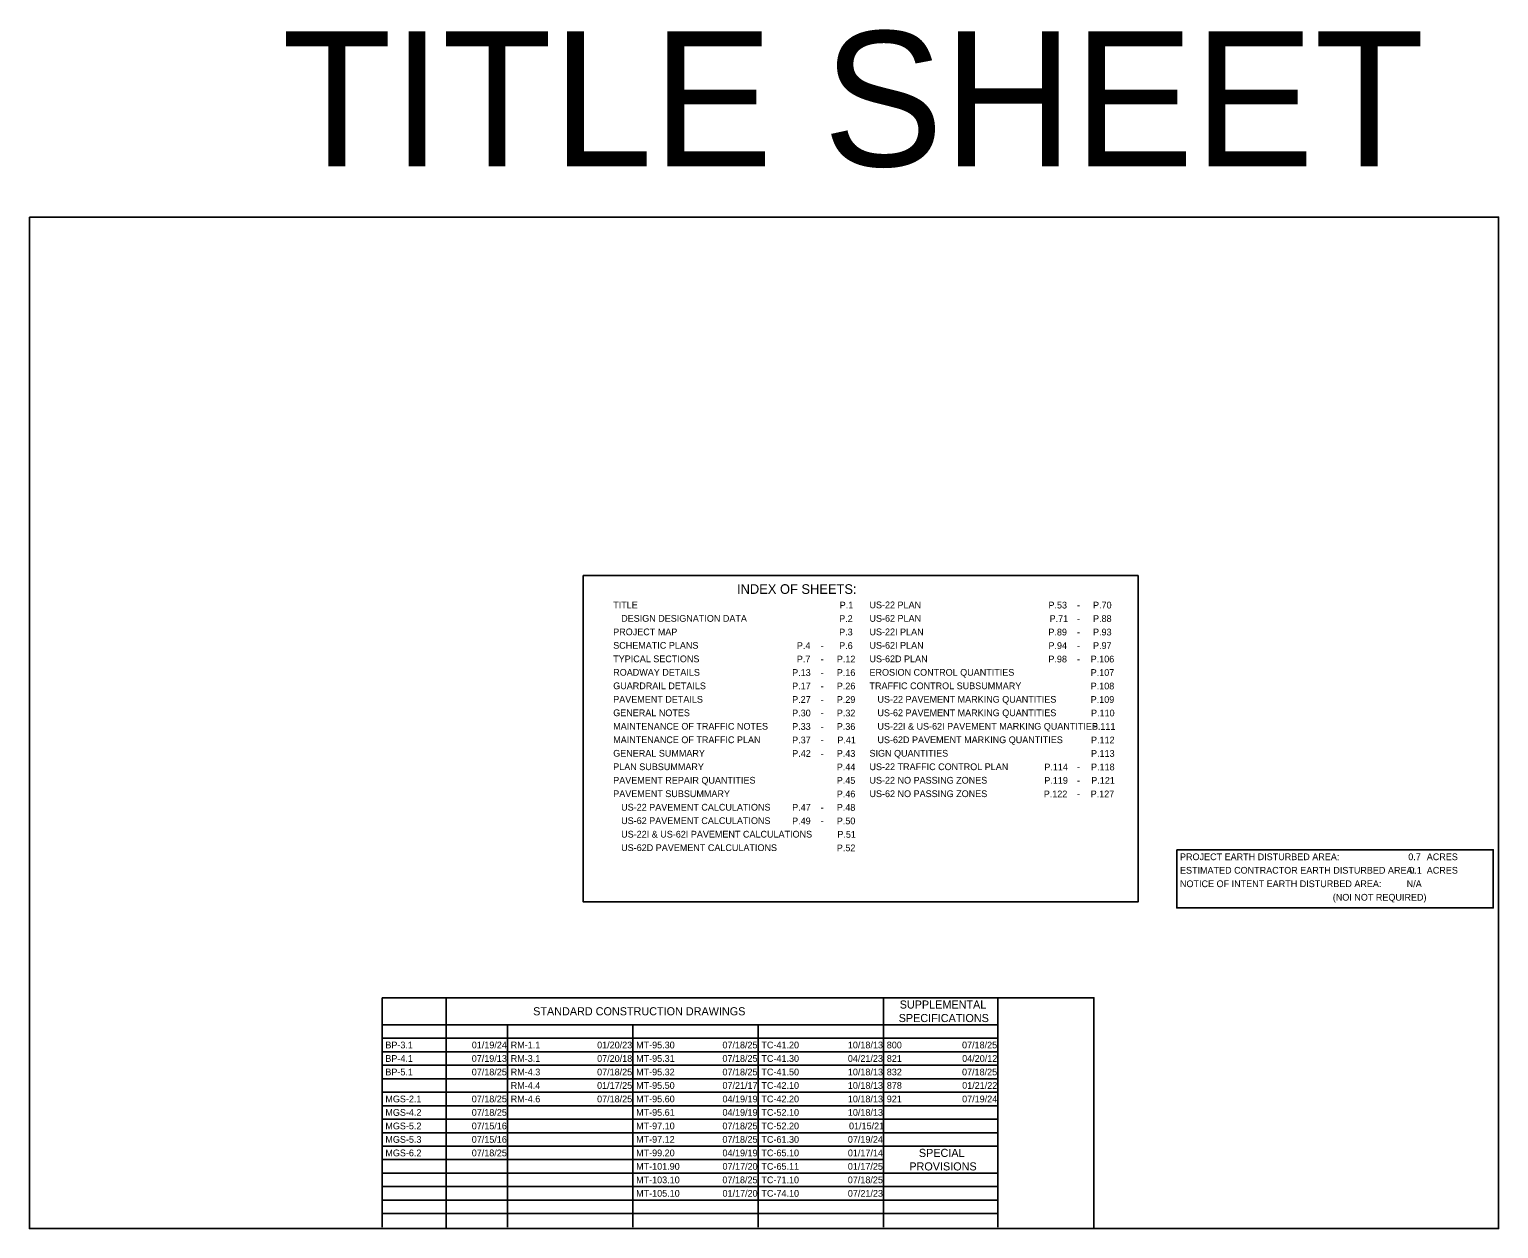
# Model space of a CAD drawing. Extents: x 12522 to 13018, y 1124 to 1902.
# Drawn here: x 12607.42 to 12637.92, y 1828.79 to 1853.69 of the extents above; entities that cross this region are included whole.
import ezdxf

# ---------------------------------------------------------------- set-up
doc = ezdxf.new("R2010")
doc.units = 0
for name, color, linetype in [('SC_Scratch1', 7, 'Continuous'), ('SH_Data', 7, 'Continuous'), ('SH_Text', 7, 'Continuous')]:
    doc.layers.add(name, color=color, linetype=linetype)

msp = doc.modelspace()

# ---------------------------------------------------------------- linework, layer by layer
at = {"layer": 'SC_Scratch1'}
for points in [[(12607.415, 1849.791), (12637.915, 1849.791), (12637.915, 1828.791), (12607.415, 1828.791)], [(12618.914, 1842.346), (12630.432, 1842.346), (12630.432, 1835.575), (12618.914, 1835.575)], [(12631.235, 1836.655), (12637.805, 1836.655), (12637.805, 1835.448), (12631.235, 1835.448)], [(12616.065, 1828.791), (12629.515, 1828.791), (12629.515, 1833.583), (12616.065, 1833.583)]]:
    msp.add_lwpolyline(points, close=True, dxfattribs=at)
at = {"layer": 'SH_Data'}
for p, q in [((12614.739, 1833.583), (12627.52, 1833.583)), ((12614.739, 1833.583), (12614.739, 1828.823)), ((12625.148, 1833.583), (12625.148, 1828.823)), ((12627.52, 1833.583), (12627.52, 1828.823)), ((12614.739, 1833.023), (12627.52, 1833.023)), ((12617.341, 1833.023), (12617.341, 1828.823)), ((12619.944, 1833.023), (12619.944, 1828.823)), ((12622.546, 1833.023), (12622.546, 1828.823)), ((12614.739, 1832.743), (12627.52, 1832.743)), ((12614.739, 1832.463), (12627.52, 1832.463)), ((12614.739, 1832.183), (12627.52, 1832.183)), ((12614.739, 1831.903), (12627.52, 1831.903)), ((12614.739, 1831.623), (12627.52, 1831.623)), ((12614.739, 1831.343), (12627.52, 1831.343)), ((12614.739, 1831.063), (12627.52, 1831.063)), ((12614.739, 1830.783), (12627.52, 1830.783)), ((12614.739, 1830.503), (12625.148, 1830.503)), ((12625.148, 1830.503), (12627.52, 1830.503)), ((12614.739, 1830.223), (12625.148, 1830.223)), ((12614.739, 1829.943), (12625.148, 1829.943)), ((12625.148, 1829.943), (12627.52, 1829.943)), ((12614.739, 1829.663), (12627.52, 1829.663)), ((12614.739, 1829.383), (12627.52, 1829.383)), ((12614.739, 1829.103), (12627.52, 1829.103))]:
    msp.add_line(p, q, dxfattribs=at)

# ---------------------------------------------------------------- texts
at = {"layer": 'SC_Scratch1'}
msp.add_text('TITLE SHEET', height=2.8, dxfattribs=at).set_placement((12612.655, 1850.845))
at = {"layer": 'SH_Text'}
for s, height, p in [('INDEX OF SHEETS:', 0.2, (12622.105, 1841.968)), ('TITLE', 0.14, (12619.535, 1841.669)), ('P.1', 0.14, (12624.237, 1841.665)), ('US-22 PLAN', 0.14, (12624.855, 1841.669)), ('P.53', 0.14, (12628.57, 1841.665)), ('-', 0.14, (12629.161, 1841.665)), ('P.70', 0.14, (12629.496, 1841.665)), ('DESIGN DESIGNATION DATA', 0.14, (12619.7, 1841.389)), ('P.2', 0.14, (12624.226, 1841.385)), ('US-62 PLAN', 0.14, (12624.855, 1841.389)), ('P.71', 0.14, (12628.594, 1841.385)), ('-', 0.14, (12629.161, 1841.385)), ('P.88', 0.14, (12629.496, 1841.385)), ('PROJECT MAP', 0.14, (12619.535, 1841.109)), ('P.3', 0.14, (12624.225, 1841.105)), ('US-22I PLAN', 0.14, (12624.855, 1841.109)), ('P.89', 0.14, (12628.569, 1841.105)), ('-', 0.14, (12629.161, 1841.105)), ('P.93', 0.14, (12629.496, 1841.105)), ('TYPICAL SECTIONS', 0.14, (12619.535, 1840.549)), ('SCHEMATIC PLANS', 0.14, (12619.535, 1840.829)), ('P.4', 0.14, (12623.348, 1840.825)), ('P.7', 0.14, (12623.347, 1840.545)), ('-', 0.14, (12623.841, 1840.825)), ('P.12', 0.14, (12624.177, 1840.545)), ('P.6', 0.14, (12624.225, 1840.825)), ('US-62I PLAN', 0.14, (12624.855, 1840.829)), ('US-62D PLAN', 0.14, (12624.855, 1840.549)), ('P.98', 0.14, (12628.569, 1840.545)), ('P.94', 0.14, (12628.57, 1840.825)), ('-', 0.14, (12629.161, 1840.825)), ('P.106', 0.14, (12629.447, 1840.545)), ('P.97', 0.14, (12629.496, 1840.825)), ('ROADWAY DETAILS', 0.14, (12619.535, 1840.269)), ('P.13', 0.14, (12623.25, 1840.265)), ('-', 0.14, (12623.841, 1840.545)), ('P.16', 0.14, (12624.176, 1840.265)), ('EROSION CONTROL QUANTITIES', 0.14, (12624.855, 1840.269)), ('-', 0.14, (12629.161, 1840.545)), ('P.107', 0.14, (12629.447, 1840.265)), ('GUARDRAIL DETAILS', 0.14, (12619.535, 1839.989)), ('P.17', 0.14, (12623.25, 1839.985)), ('-', 0.14, (12623.841, 1840.265)), ('P.26', 0.14, (12624.176, 1839.985)), ('TRAFFIC CONTROL SUBSUMMARY', 0.14, (12624.855, 1839.989)), ('P.108', 0.14, (12629.447, 1839.985)), ('PAVEMENT DETAILS', 0.14, (12619.535, 1839.709)), ('P.27', 0.14, (12623.25, 1839.705)), ('-', 0.14, (12623.841, 1839.985)), ('-', 0.14, (12623.841, 1839.705)), ('P.29', 0.14, (12624.176, 1839.705)), ('US-22 PAVEMENT MARKING QUANTITIES', 0.14, (12625.02, 1839.709)), ('P.109', 0.14, (12629.447, 1839.705)), ('GENERAL NOTES', 0.14, (12619.535, 1839.429)), ('P.30', 0.14, (12623.25, 1839.425)), ('-', 0.14, (12623.841, 1839.425)), ('P.32', 0.14, (12624.177, 1839.425)), ('US-62 PAVEMENT MARKING QUANTITIES', 0.14, (12625.02, 1839.429)), ('P.110', 0.14, (12629.454, 1839.425)), ('MAINTENANCE OF TRAFFIC NOTES', 0.14, (12619.535, 1839.149)), ('P.33', 0.14, (12623.25, 1839.145)), ('-', 0.14, (12623.841, 1839.145)), ('P.36', 0.14, (12624.176, 1839.145)), ('US-22I & US-62I PAVEMENT MARKING QUANTITIES', 0.14, (12625.02, 1839.149)), ('P.111', 0.14, (12629.472, 1839.145)), ('MAINTENANCE OF TRAFFIC PLAN', 0.14, (12619.535, 1838.869)), ('P.37', 0.14, (12623.25, 1838.865)), ('-', 0.14, (12623.841, 1838.865)), ('P.41', 0.14, (12624.188, 1838.865)), ('US-62D PAVEMENT MARKING QUANTITIES', 0.14, (12625.02, 1838.869)), ('P.112', 0.14, (12629.454, 1838.865)), ('GENERAL SUMMARY', 0.14, (12619.535, 1838.589)), ('P.42', 0.14, (12623.251, 1838.585)), ('-', 0.14, (12623.841, 1838.585)), ('P.43', 0.14, (12624.176, 1838.585)), ('SIGN QUANTITIES', 0.14, (12624.855, 1838.589)), ('P.113', 0.14, (12629.454, 1838.585)), ('PLAN SUBSUMMARY', 0.14, (12619.535, 1838.309)), ('P.44', 0.14, (12624.176, 1838.305)), ('US-22 TRAFFIC CONTROL PLAN', 0.14, (12624.855, 1838.309)), ('P.114', 0.14, (12628.485, 1838.305)), ('-', 0.14, (12629.161, 1838.305)), ('P.118', 0.14, (12629.454, 1838.305)), ('PAVEMENT REPAIR QUANTITIES', 0.14, (12619.535, 1838.029)), ('P.45', 0.14, (12624.176, 1838.025)), ('US-22 NO PASSING ZONES', 0.14, (12624.855, 1838.029)), ('P.119', 0.14, (12628.485, 1838.025)), ('-', 0.14, (12629.161, 1838.025)), ('P.121', 0.14, (12629.459, 1838.025)), ('PAVEMENT SUBSUMMARY', 0.14, (12619.535, 1837.749)), ('P.46', 0.14, (12624.176, 1837.745)), ('US-62 NO PASSING ZONES', 0.14, (12624.855, 1837.749)), ('P.122', 0.14, (12628.473, 1837.745)), ('-', 0.14, (12629.161, 1837.745)), ('P.127', 0.14, (12629.447, 1837.745)), ('US-22 PAVEMENT CALCULATIONS', 0.14, (12619.7, 1837.469)), ('US-62 PAVEMENT CALCULATIONS', 0.14, (12619.7, 1837.189)), ('P.47', 0.14, (12623.25, 1837.465)), ('P.49', 0.14, (12623.249, 1837.185)), ('-', 0.14, (12623.841, 1837.465)), ('P.48', 0.14, (12624.176, 1837.465)), ('P.50', 0.14, (12624.176, 1837.185)), ('US-22I & US-62I PAVEMENT CALCULATIONS', 0.14, (12619.7, 1836.909)), ('-', 0.14, (12623.841, 1837.185)), ('P.51', 0.14, (12624.188, 1836.905)), ('US-62D PAVEMENT CALCULATIONS', 0.14, (12619.7, 1836.629)), ('P.52', 0.14, (12624.177, 1836.625)), ('PROJECT EARTH DISTURBED AREA:', 0.14, (12631.301, 1836.44)), ('0.7', 0.14, (12636.04, 1836.44)), ('ACRES', 0.14, (12636.424, 1836.44)), ('ESTIMATED CONTRACTOR EARTH DISTURBED AREA:', 0.14, (12631.301, 1836.16)), ('0.1', 0.14, (12636.061, 1836.16)), ('ACRES', 0.14, (12636.424, 1836.16)), ('NOTICE OF INTENT EARTH DISTURBED AREA:', 0.14, (12631.301, 1835.88)), ('N/A', 0.14, (12636.007, 1835.88)), ('(NOI NOT REQUIRED)', 0.14, (12634.473, 1835.6)), ('STANDARD CONSTRUCTION DRAWINGS', 0.168, (12617.873, 1833.219)), ('SUPPLEMENTAL', 0.168, (12625.482, 1833.359)), ('SPECIFICATIONS', 0.168, (12625.461, 1833.079)), ('BP-3.1', 0.14, (12614.805, 1832.533)), ('01/19/24', 0.14, (12616.599, 1832.533)), ('RM-1.1', 0.14, (12617.407, 1832.533)), ('01/20/23', 0.14, (12619.201, 1832.533)), ('MT-95.30', 0.14, (12620.01, 1832.533)), ('07/18/25', 0.14, (12621.802, 1832.533)), ('TC-41.20', 0.14, (12622.612, 1832.533)), ('10/18/13', 0.14, (12624.406, 1832.533)), ('800', 0.14, (12625.214, 1832.533)), ('07/18/25', 0.14, (12626.776, 1832.533)), ('BP-4.1', 0.14, (12614.805, 1832.253)), ('07/19/13', 0.14, (12616.598, 1832.253)), ('RM-3.1', 0.14, (12617.407, 1832.253)), ('07/20/18', 0.14, (12619.201, 1832.253)), ('MT-95.31', 0.14, (12620.01, 1832.253)), ('07/18/25', 0.14, (12621.802, 1832.253)), ('TC-41.30', 0.14, (12622.612, 1832.253)), ('04/21/23', 0.14, (12624.406, 1832.253)), ('821', 0.14, (12625.214, 1832.253)), ('04/20/12', 0.14, (12626.779, 1832.253)), ('BP-5.1', 0.14, (12614.805, 1831.973)), ('07/18/25', 0.14, (12616.598, 1831.973)), ('RM-4.3', 0.14, (12617.407, 1831.973)), ('RM-4.4', 0.14, (12617.407, 1831.693)), ('07/18/25', 0.14, (12619.2, 1831.973)), ('01/17/25', 0.14, (12619.2, 1831.693)), ('MT-95.32', 0.14, (12620.01, 1831.973)), ('MT-95.50', 0.14, (12620.01, 1831.693)), ('07/18/25', 0.14, (12621.802, 1831.973)), ('07/21/17', 0.14, (12621.803, 1831.693)), ('TC-41.50', 0.14, (12622.612, 1831.973)), ('TC-42.10', 0.14, (12622.612, 1831.693)), ('10/18/13', 0.14, (12624.406, 1831.973)), ('10/18/13', 0.14, (12624.406, 1831.693)), ('832', 0.14, (12625.214, 1831.973)), ('878', 0.14, (12625.214, 1831.693)), ('07/18/25', 0.14, (12626.776, 1831.973)), ('01/21/22', 0.14, (12626.779, 1831.693)), ('MGS-2.1', 0.14, (12614.805, 1831.413)), ('07/18/25', 0.14, (12616.598, 1831.413)), ('RM-4.6', 0.14, (12617.407, 1831.413)), ('07/18/25', 0.14, (12619.2, 1831.413)), ('MT-95.60', 0.14, (12620.01, 1831.413)), ('04/19/19', 0.14, (12621.803, 1831.413)), ('TC-42.20', 0.14, (12622.612, 1831.413)), ('10/18/13', 0.14, (12624.406, 1831.413)), ('921', 0.14, (12625.214, 1831.413)), ('07/19/24', 0.14, (12626.778, 1831.413)), ('MGS-4.2', 0.14, (12614.805, 1831.133)), ('07/18/25', 0.14, (12616.598, 1831.133)), ('MT-95.61', 0.14, (12620.01, 1831.133)), ('04/19/19', 0.14, (12621.803, 1831.133)), ('TC-52.10', 0.14, (12622.612, 1831.133)), ('10/18/13', 0.14, (12624.406, 1831.133)), ('MGS-5.2', 0.14, (12614.805, 1830.853)), ('07/15/16', 0.14, (12616.598, 1830.853)), ('MT-97.10', 0.14, (12620.01, 1830.853)), ('07/18/25', 0.14, (12621.802, 1830.853)), ('TC-52.20', 0.14, (12622.612, 1830.853)), ('01/15/21', 0.14, (12624.43, 1830.853)), ('MGS-5.3', 0.14, (12614.805, 1830.573)), ('07/15/16', 0.14, (12616.598, 1830.573)), ('MT-97.12', 0.14, (12620.01, 1830.573)), ('07/18/25', 0.14, (12621.802, 1830.573)), ('TC-61.30', 0.14, (12622.612, 1830.573)), ('07/19/24', 0.14, (12624.406, 1830.573)), ('MGS-6.2', 0.14, (12614.805, 1830.293)), ('07/18/25', 0.14, (12616.598, 1830.293)), ('MT-99.20', 0.14, (12620.01, 1830.293)), ('04/19/19', 0.14, (12621.803, 1830.293)), ('TC-65.10', 0.14, (12622.612, 1830.293)), ('01/17/14', 0.14, (12624.406, 1830.293)), ('SPECIAL', 0.168, (12625.88, 1830.279)), ('MT-101.90', 0.14, (12620.01, 1830.013)), ('07/17/20', 0.14, (12621.804, 1830.013)), ('TC-65.11', 0.14, (12622.612, 1830.013)), ('01/17/25', 0.14, (12624.405, 1830.013)), ('PROVISIONS', 0.168, (12625.682, 1829.999)), ('MT-103.10', 0.14, (12620.01, 1829.733)), ('07/18/25', 0.14, (12621.802, 1829.733)), ('TC-71.10', 0.14, (12622.612, 1829.733)), ('07/18/25', 0.14, (12624.405, 1829.733)), ('MT-105.10', 0.14, (12620.01, 1829.453)), ('01/17/20', 0.14, (12621.804, 1829.453)), ('TC-74.10', 0.14, (12622.612, 1829.453)), ('07/21/23', 0.14, (12624.406, 1829.453))]:
    msp.add_text(s, height=height, dxfattribs=at).set_placement(p)

doc.saveas('drawing.dxf')
